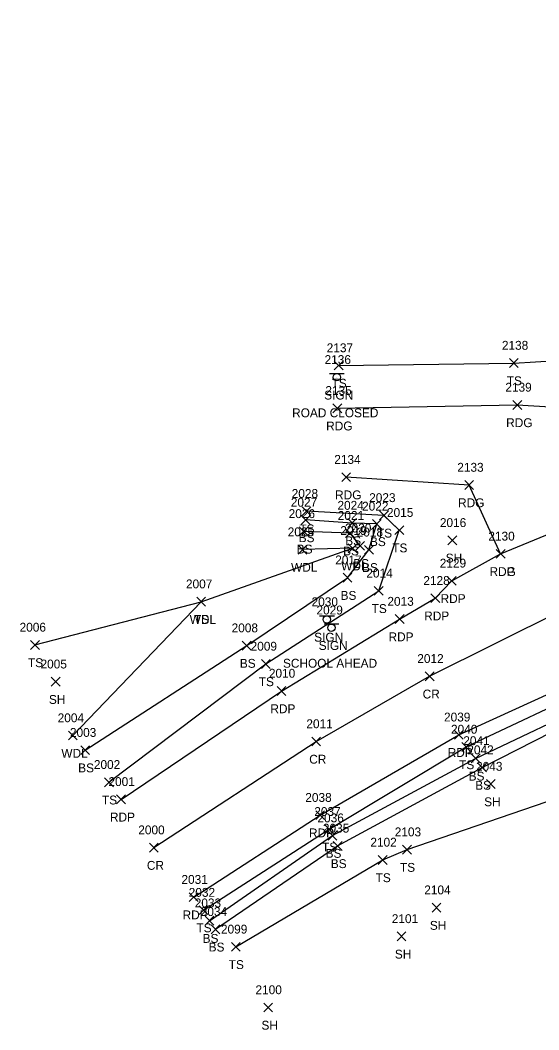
# Model space of a CAD drawing. Extents: x 1699408 to 1700423, y 840176 to 841410.
# Drawn here: x 1699408 to 1699525, y 840176.2 to 840403.9 of the extents above; entities that cross this region are included whole.
import ezdxf

# ---------------------------------------------------------------- set-up
doc = ezdxf.new("R2010")
doc.units = 0
for name, color, linetype in [('L_A', 7, 'Continuous'), ('L_I', 7, 'Continuous'), ('L_TIC', 7, 'Continuous'), ('LAWA', 7, 'Continuous'), ('LELB', 7, 'Continuous'), ('P_A', 7, 'Continuous'), ('P_I', 7, 'Continuous'), ('P_TIC', 7, 'Continuous'), ('PET', 7, 'Continuous'), ('PEU', 7, 'Continuous'), ('PRC', 7, 'Continuous'), ('S_A', 7, 'Continuous'), ('S_C', 7, 'Continuous'), ('S_I', 7, 'Continuous'), ('SSGN', 7, 'Continuous')]:
    doc.layers.add(name, color=color, linetype=linetype)

msp = doc.modelspace()

# ---------------------------------------------------------------- linework, layer by layer
at = {"layer": 'L_TIC'}
for points in [[(1699478.81, 840325.06), (1699480.81, 840327.06)], [(1699480.81, 840325.06), (1699478.81, 840327.06)], [(1699518.34, 840325.61), (1699520.34, 840327.61)], [(1699520.34, 840325.61), (1699518.34, 840327.61)], [(1699471.56, 840292.2), (1699473.56, 840294.2)], [(1699473.56, 840292.2), (1699471.56, 840294.2)], [(1699471.36, 840290.22), (1699473.36, 840292.22)], [(1699473.36, 840290.22), (1699471.36, 840292.22)], [(1699489.04, 840291.26), (1699491.04, 840293.26)], [(1699491.04, 840291.26), (1699489.04, 840293.26)], [(1699470.92, 840287.65), (1699472.92, 840289.65)], [(1699472.92, 840287.65), (1699470.92, 840289.65)], [(1699481.87, 840289.52), (1699483.87, 840291.52)], [(1699483.87, 840289.52), (1699481.87, 840291.52)], [(1699487.44, 840289.33), (1699489.44, 840291.33)], [(1699489.44, 840289.33), (1699487.44, 840291.33)], [(1699492.5, 840287.92), (1699494.5, 840289.92)], [(1699494.5, 840287.92), (1699492.5, 840289.92)], [(1699481.39, 840287.24), (1699483.39, 840289.24)], [(1699483.39, 840287.24), (1699481.39, 840289.24)], [(1699504.48, 840285.63), (1699506.48, 840287.63)], [(1699506.48, 840285.63), (1699504.48, 840287.63)], [(1699470.65, 840283.54), (1699472.65, 840285.54)], [(1699472.65, 840283.54), (1699470.65, 840285.54)], [(1699481.97, 840283.84), (1699483.97, 840285.84)], [(1699483.97, 840283.84), (1699481.97, 840285.84)], [(1699483.67, 840284.4), (1699485.67, 840286.4)], [(1699485.67, 840284.4), (1699483.67, 840286.4)], [(1699485.65, 840283.49), (1699487.65, 840285.49)], [(1699487.65, 840283.49), (1699485.65, 840285.49)], [(1699480.81, 840277.21), (1699482.81, 840279.21)], [(1699482.81, 840277.21), (1699480.81, 840279.21)], [(1699487.85, 840274.24), (1699489.85, 840276.24)], [(1699489.85, 840274.24), (1699487.85, 840276.24)], [(1699447.78, 840271.8), (1699449.78, 840273.8)], [(1699449.78, 840271.8), (1699447.78, 840273.8)], [(1699447.78, 840271.8), (1699449.78, 840273.8)], [(1699449.78, 840271.8), (1699447.78, 840273.8)], [(1699410.29, 840262.04), (1699412.29, 840264.04)], [(1699412.29, 840262.04), (1699410.29, 840264.04)], [(1699458.07, 840261.89), (1699460.07, 840263.89)], [(1699460.07, 840261.89), (1699458.07, 840263.89)], [(1699462.38, 840257.75), (1699464.38, 840259.75)], [(1699464.38, 840257.75), (1699462.38, 840259.75)], [(1699414.96, 840253.74), (1699416.96, 840255.74)], [(1699416.96, 840253.74), (1699414.96, 840255.74)], [(1699418.82, 840241.61), (1699420.82, 840243.61)], [(1699420.82, 840241.61), (1699418.82, 840243.61)], [(1699421.6, 840238.31), (1699423.6, 840240.31)], [(1699423.6, 840238.31), (1699421.6, 840240.31)], [(1699507.6, 840239.03), (1699509.6, 840241.03)], [(1699509.6, 840239.03), (1699507.6, 840241.03)], [(1699509.71, 840236.45), (1699511.71, 840238.45)], [(1699511.71, 840236.45), (1699509.71, 840238.45)], [(1699511.19, 840234.39), (1699513.19, 840236.39)], [(1699513.19, 840234.39), (1699511.19, 840236.39)], [(1699426.99, 840231.07), (1699428.99, 840233.07)], [(1699428.99, 840231.07), (1699426.99, 840233.07)], [(1699513.16, 840230.67), (1699515.16, 840232.67)], [(1699515.16, 840230.67), (1699513.16, 840232.67)], [(1699476.66, 840220.47), (1699478.66, 840222.47)], [(1699478.66, 840220.47), (1699476.66, 840222.47)], [(1699477.43, 840219.04), (1699479.43, 840221.04)], [(1699479.43, 840219.04), (1699477.43, 840221.04)], [(1699478.59, 840216.72), (1699480.59, 840218.72)], [(1699480.59, 840216.72), (1699478.59, 840218.72)], [(1699494.24, 840215.88), (1699496.24, 840217.88)], [(1699496.24, 840215.88), (1699494.24, 840217.88)], [(1699488.75, 840213.55), (1699490.75, 840215.55)], [(1699490.75, 840213.55), (1699488.75, 840215.55)], [(1699448.32, 840202.24), (1699450.32, 840204.24)], [(1699450.32, 840202.24), (1699448.32, 840204.24)], [(1699500.9, 840202.8), (1699502.9, 840204.8)], [(1699502.9, 840202.8), (1699500.9, 840204.8)], [(1699449.68, 840199.86), (1699451.68, 840201.86)], [(1699451.68, 840199.86), (1699449.68, 840201.86)], [(1699451.04, 840197.91), (1699453.04, 840199.91)], [(1699453.04, 840197.91), (1699451.04, 840199.91)], [(1699493.01, 840196.31), (1699495.01, 840198.31)], [(1699495.01, 840196.31), (1699493.01, 840198.31)], [(1699455.6, 840193.95), (1699457.6, 840195.95)], [(1699457.6, 840193.95), (1699455.6, 840195.95)], [(1699462.91, 840180.28), (1699464.91, 840182.28)], [(1699464.91, 840180.28), (1699462.91, 840182.28)]]:
    msp.add_lwpolyline(points, dxfattribs=at)
at = {"layer": 'LAWA'}
msp.add_lwpolyline([(1699419.82, 840242.61), (1699448.78, 840272.8), (1699482.97, 840284.84), (1699471.65, 840284.54)], dxfattribs=at)
at = {"layer": 'LELB'}
for points in [[(1699479.81, 840326.06), (1699519.34, 840326.61), (1699568.26, 840329.58), (1699587.28, 840330.32), (1699620.45, 840326.5), (1699668.14, 840330.52), (1699701.48, 840332.44), (1699728.48, 840335.43)], [(1699449.32, 840203.24), (1699477.66, 840221.47), (1699508.6, 840240.03), (1699538.28, 840254.01), (1699565.8, 840264.7), (1699593.44, 840273.59), (1699619.93, 840280.17), (1699647.78, 840284.89), (1699680.49, 840289.58), (1699709.99, 840292.62), (1699741.26, 840296.11), (1699773.28, 840299.24), (1699807.33, 840304.54), (1699837.32, 840309.49), (1699840.77, 840304.78), (1699846.98, 840289.91), (1699852.46, 840279.79)], [(1699450.68, 840200.86), (1699478.43, 840220.04), (1699510.71, 840237.45), (1699539.18, 840250.98), (1699567.45, 840262.15), (1699594.13, 840270.62), (1699621.67, 840276.44), (1699649, 840280.25), (1699681.32, 840285.34), (1699711.01, 840288.64), (1699741.71, 840291.52), (1699773.21, 840296.35), (1699808.7, 840300.3), (1699836.43, 840305.42), (1699838.09, 840303.05), (1699840.88, 840298.91), (1699844.69, 840290.05), (1699850.95, 840279.03)], [(1699452.04, 840198.91), (1699479.59, 840217.72), (1699512.19, 840235.39), (1699539.84, 840249.47), (1699568.3, 840260.42), (1699595.02, 840268.85), (1699623.34, 840272.03), (1699650.02, 840274.02), (1699683.39, 840277.43), (1699712.27, 840281.78), (1699743, 840285.37), (1699773.99, 840291.21), (1699809.19, 840296.39), (1699836.05, 840299.39), (1699842.76, 840289.31), (1699848.51, 840278.09)], [(1699427.99, 840232.07), (1699463.38, 840258.75), (1699488.85, 840275.24), (1699493.5, 840288.92), (1699490.04, 840292.26), (1699472.56, 840293.2)], [(1699422.6, 840239.31), (1699459.07, 840262.89), (1699481.81, 840278.21), (1699486.65, 840284.49), (1699488.44, 840290.33), (1699482.87, 840290.52), (1699472.36, 840291.22)], [(1699484.67, 840285.4), (1699482.39, 840288.24), (1699471.92, 840288.65)], [(1699411.29, 840263.04), (1699448.78, 840272.8)], [(1699456.6, 840194.95), (1699489.75, 840214.55), (1699495.24, 840216.88), (1699529.29, 840228.56), (1699553.24, 840234.35), (1699584.46, 840240.65), (1699620, 840241.73), (1699625.43, 840235.65), (1699633.39, 840226.83)]]:
    msp.add_lwpolyline(points, dxfattribs=at)
at = {"layer": 'P_TIC'}
for points in [[(1699478.51, 840315.42), (1699480.51, 840317.42)], [(1699480.51, 840315.42), (1699478.51, 840317.42)], [(1699519.13, 840316.16), (1699521.13, 840318.16)], [(1699521.13, 840316.16), (1699519.13, 840318.16)], [(1699480.52, 840299.88), (1699482.52, 840301.88)], [(1699482.52, 840299.88), (1699480.52, 840301.88)], [(1699508.27, 840298.1), (1699510.27, 840300.1)], [(1699510.27, 840298.1), (1699508.27, 840300.1)], [(1699515.37, 840282.58), (1699517.37, 840284.58)], [(1699517.37, 840282.58), (1699515.37, 840284.58)], [(1699515.37, 840282.58), (1699517.37, 840284.58)], [(1699517.37, 840282.58), (1699515.37, 840284.58)], [(1699504.33, 840276.49), (1699506.33, 840278.49)], [(1699506.33, 840276.49), (1699504.33, 840278.49)], [(1699500.63, 840272.58), (1699502.63, 840274.58)], [(1699502.63, 840272.58), (1699500.63, 840274.58)], [(1699492.58, 840267.87), (1699494.58, 840269.87)], [(1699494.58, 840267.87), (1699492.58, 840269.87)], [(1699499.34, 840254.97), (1699501.34, 840256.97)], [(1699501.34, 840254.97), (1699499.34, 840256.97)], [(1699465.92, 840251.65), (1699467.92, 840253.65)], [(1699467.92, 840251.65), (1699465.92, 840253.65)], [(1699505.94, 840241.78), (1699507.94, 840243.78)], [(1699507.94, 840241.78), (1699505.94, 840243.78)], [(1699473.74, 840240.27), (1699475.74, 840242.27)], [(1699475.74, 840240.27), (1699473.74, 840242.27)], [(1699429.72, 840227.22), (1699431.72, 840229.22)], [(1699431.72, 840227.22), (1699429.72, 840229.22)], [(1699474.63, 840223.65), (1699476.63, 840225.65)], [(1699476.63, 840223.65), (1699474.63, 840225.65)], [(1699437.11, 840216.33), (1699439.11, 840218.33)], [(1699439.11, 840216.33), (1699437.11, 840218.33)], [(1699446.11, 840205.16), (1699448.11, 840207.16)], [(1699448.11, 840205.16), (1699446.11, 840207.16)]]:
    msp.add_lwpolyline(points, dxfattribs=at)
at = {"layer": 'PET'}
for points in [[(1699430.72, 840228.22), (1699466.92, 840252.65), (1699493.58, 840268.87), (1699501.63, 840273.58), (1699505.33, 840277.49), (1699516.37, 840283.58), (1699542.26, 840294.23), (1699569.87, 840304.55), (1699598.29, 840312.45), (1699620.64, 840316.32), (1699670.9, 840322.33), (1699702.16, 840325.07), (1699741.15, 840329.16), (1699780.55, 840332.75), (1699814.05, 840338.23), (1699848.8, 840345.35), (1699873.3, 840351.35), (1699914.22, 840362.32), (1699930.57, 840367.02), (1699959.45, 840375.82), (1699990.91, 840385.72), (1700021.62, 840396.71), (1700043.81, 840403.93)], [(1699447.11, 840206.16), (1699475.63, 840224.65), (1699506.94, 840242.78), (1699536.09, 840256.08), (1699564.51, 840267.73), (1699591.88, 840277.12), (1699619.21, 840283.47), (1699647.22, 840288.99), (1699679.73, 840293.47), (1699710.33, 840296.95), (1699740.62, 840299.68), (1699772.35, 840302.79), (1699806.37, 840308.43), (1699836.08, 840313.39), (1699858.12, 840318.39), (1699877.08, 840323.18), (1699900.35, 840329.36), (1699935.97, 840340.61), (1699968.58, 840349.28), (1700000.7, 840359.42), (1700031.35, 840369.03)]]:
    msp.add_lwpolyline(points, dxfattribs=at)
at = {"layer": 'PEU'}
for points in [[(1699479.51, 840316.42), (1699520.13, 840317.16), (1699537.65, 840316.15), (1699569.4, 840315.83), (1699598.29, 840312.45)], [(1699516.37, 840283.58), (1699509.27, 840299.1), (1699481.52, 840300.88)]]:
    msp.add_lwpolyline(points, dxfattribs=at)
at = {"layer": 'PRC'}
msp.add_lwpolyline([(1699438.11, 840217.33), (1699474.74, 840241.27), (1699500.34, 840255.97), (1699530.26, 840270.89), (1699558.33, 840282.59), (1699589.24, 840292.75), (1699616.86, 840299.45), (1699644.68, 840304.26), (1699678.81, 840308.53), (1699708.26, 840311.1), (1699739.11, 840314.27), (1699770.93, 840317.73), (1699804.23, 840322.43), (1699833.64, 840328), (1699873.5, 840337.02), (1699896.6, 840342.97), (1699933.32, 840353.07), (1699963.1, 840362.17), (1699996.81, 840372.51), (1700026.94, 840382.38)], dxfattribs=at)
at = {"layer": 'SSGN'}
for p, q in [((1699477.76, 840324.24), (1699481.09, 840324.24)), ((1699479.41, 840323.41), (1699479.41, 840323.41)), ((1699475.51, 840269.63), (1699478.84, 840269.63)), ((1699477.15, 840268.8), (1699477.15, 840268.8)), ((1699476.53, 840267.77), (1699479.86, 840267.77)), ((1699478.18, 840266.93), (1699478.18, 840266.93))]:
    msp.add_line(p, q, dxfattribs=at)
for centre in [(1699479.41, 840323.41), (1699477.15, 840268.8), (1699478.18, 840266.93)]:
    msp.add_circle(centre, 0.833, dxfattribs=at)

# ---------------------------------------------------------------- texts
at = {"layer": 'L_A'}
for s, p in [('TS', (1699517.75, 840321.61)), ('TS', (1699478.22, 840321.06)), ('TS', (1699470.97, 840288.2)), ('TS', (1699488.45, 840287.26)), ('BS', (1699470.8, 840286.22)), ('BS', (1699481.31, 840285.52)), ('BS', (1699486.88, 840285.33)), ('BS', (1699470.36, 840283.65)), ('BS', (1699480.83, 840283.24)), ('TS', (1699491.91, 840283.92)), ('BS', (1699483.11, 840280.4)), ('SH', (1699503.97, 840281.63)), ('WDL', (1699469.07, 840279.54)), ('WDL', (1699480.39, 840279.84)), ('BS', (1699485.1, 840279.49)), ('BS', (1699480.25, 840273.21)), ('TS', (1699487.26, 840270.24)), ('WDL', (1699446.2, 840267.8)), ('TS', (1699447.19, 840267.8)), ('TS', (1699409.7, 840258.04)), ('BS', (1699457.51, 840257.89)), ('TS', (1699461.79, 840253.75)), ('SH', (1699414.44, 840249.74)), ('WDL', (1699417.24, 840237.61)), ('TS', (1699507, 840235.03)), ('BS', (1699421.04, 840234.31)), ('BS', (1699509.15, 840232.45)), ('BS', (1699510.63, 840230.39)), ('TS', (1699426.4, 840227.07)), ('SH', (1699512.65, 840226.67)), ('TS', (1699476.07, 840216.47)), ('BS', (1699476.87, 840215.04)), ('BS', (1699478.04, 840212.72)), ('TS', (1699493.65, 840211.88)), ('TS', (1699488.16, 840209.55)), ('SH', (1699500.39, 840198.8)), ('TS', (1699447.73, 840198.24)), ('BS', (1699449.12, 840195.86)), ('BS', (1699450.48, 840193.91)), ('SH', (1699492.5, 840192.31)), ('TS', (1699455.01, 840189.95)), ('SH', (1699462.4, 840176.28))]:
    msp.add_text(s, height=2, dxfattribs=at).set_placement(p)
at = {"layer": 'L_I'}
for s, p in [('2137', (1699477.12, 840329.06)), ('2138', (1699516.65, 840329.61)), ('2027', (1699469.02, 840294.22)), ('2028', (1699469.22, 840296.2)), ('2023', (1699486.7, 840295.26)), ('2024', (1699479.54, 840293.52)), ('2022', (1699485.1, 840293.33)), ('2015', (1699490.72, 840291.92)), ('2026', (1699468.53, 840291.65)), ('2021', (1699479.61, 840291.24)), ('2016', (1699502.66, 840289.63)), ('2025', (1699468.32, 840287.54)), ('2019', (1699480.19, 840287.84)), ('2020', (1699481.25, 840288.4)), ('2018', (1699483.88, 840287.49)), ('2017', (1699479.04, 840281.21)), ('2014', (1699486.07, 840278.24)), ('2007', (1699445.36, 840275.8)), ('2007', (1699445.36, 840275.8)), ('2006', (1699407.82, 840266.04)), ('2008', (1699455.66, 840265.89)), ('2009', (1699459.95, 840261.75)), ('2005', (1699412.54, 840257.74)), ('2004', (1699416.41, 840245.61)), ('2003', (1699419.18, 840242.31)), ('2040', (1699505.17, 840243.03)), ('2041', (1699507.94, 840240.45)), ('2042', (1699508.85, 840238.39)), ('2002', (1699424.58, 840235.07)), ('2043', (1699510.82, 840234.67)), ('2037', (1699474.32, 840224.47)), ('2036', (1699475.03, 840223.04)), ('2035', (1699476.26, 840220.72)), ('2103', (1699492.47, 840219.88)), ('2102', (1699486.97, 840217.55)), ('2032', (1699445.98, 840206.24)), ('2104', (1699499.13, 840206.8)), ('2033', (1699447.34, 840203.86)), ('2034', (1699448.7, 840201.91)), ('2101', (1699491.8, 840200.31)), ('2099', (1699453.26, 840197.95)), ('2100', (1699461.05, 840184.28))]:
    msp.add_text(s, height=2, dxfattribs=at).set_placement(p)
at = {"layer": 'P_A'}
for s, p in [('RDG', (1699477, 840311.42)), ('RDG', (1699517.62, 840312.16)), ('RDG', (1699479.01, 840295.88)), ('RDG', (1699506.76, 840294.1)), ('RDG', (1699513.86, 840278.58)), ('RDP', (1699513.86, 840278.58)), ('RDP', (1699502.82, 840272.49)), ('RDP', (1699499.12, 840268.58)), ('RDP', (1699491.07, 840263.87)), ('CR', (1699498.77, 840250.97)), ('RDP', (1699464.41, 840247.65)), ('RDP', (1699504.42, 840237.78)), ('CR', (1699473.17, 840236.27)), ('RDP', (1699428.21, 840223.22)), ('RDP', (1699473.12, 840219.65)), ('CR', (1699436.54, 840212.33)), ('RDP', (1699444.6, 840201.16))]:
    msp.add_text(s, height=2, dxfattribs=at).set_placement(p)
at = {"layer": 'P_I'}
for s, p in [('2135', (1699476.82, 840319.42)), ('2139', (1699517.43, 840320.16)), ('2134', (1699478.83, 840303.88)), ('2133', (1699506.58, 840302.1)), ('2130', (1699513.59, 840286.58)), ('2130', (1699513.59, 840286.58)), ('2129', (1699502.63, 840280.49)), ('2128', (1699498.93, 840276.58)), ('2013', (1699490.81, 840271.87)), ('2012', (1699497.56, 840258.97)), ('2010', (1699464.07, 840255.65)), ('2011', (1699472.53, 840244.27)), ('2039', (1699503.59, 840245.78)), ('2001', (1699427.87, 840231.22)), ('2038', (1699472.29, 840227.65)), ('2000', (1699434.6, 840220.33)), ('2031', (1699444.34, 840209.16))]:
    msp.add_text(s, height=2, dxfattribs=at).set_placement(p)
at = {"layer": 'S_A'}
for p in [(1699476.55, 840318.39), (1699474.29, 840263.78), (1699475.31, 840261.91)]:
    msp.add_text('SIGN', height=2, dxfattribs=at).set_placement(p)
at = {"layer": 'S_C'}
for s, p in [('ROAD CLOSED', (1699469.32, 840314.39)), ('SCHOOL AHEAD', (1699467.25, 840257.91))]:
    msp.add_text(s, height=2, dxfattribs=at).set_placement(p)
at = {"layer": 'S_I'}
for s, p in [('2136', (1699476.64, 840326.39)), ('2030', (1699473.71, 840271.78)), ('2029', (1699474.81, 840269.91))]:
    msp.add_text(s, height=2, dxfattribs=at).set_placement(p)

doc.saveas('drawing.dxf')
